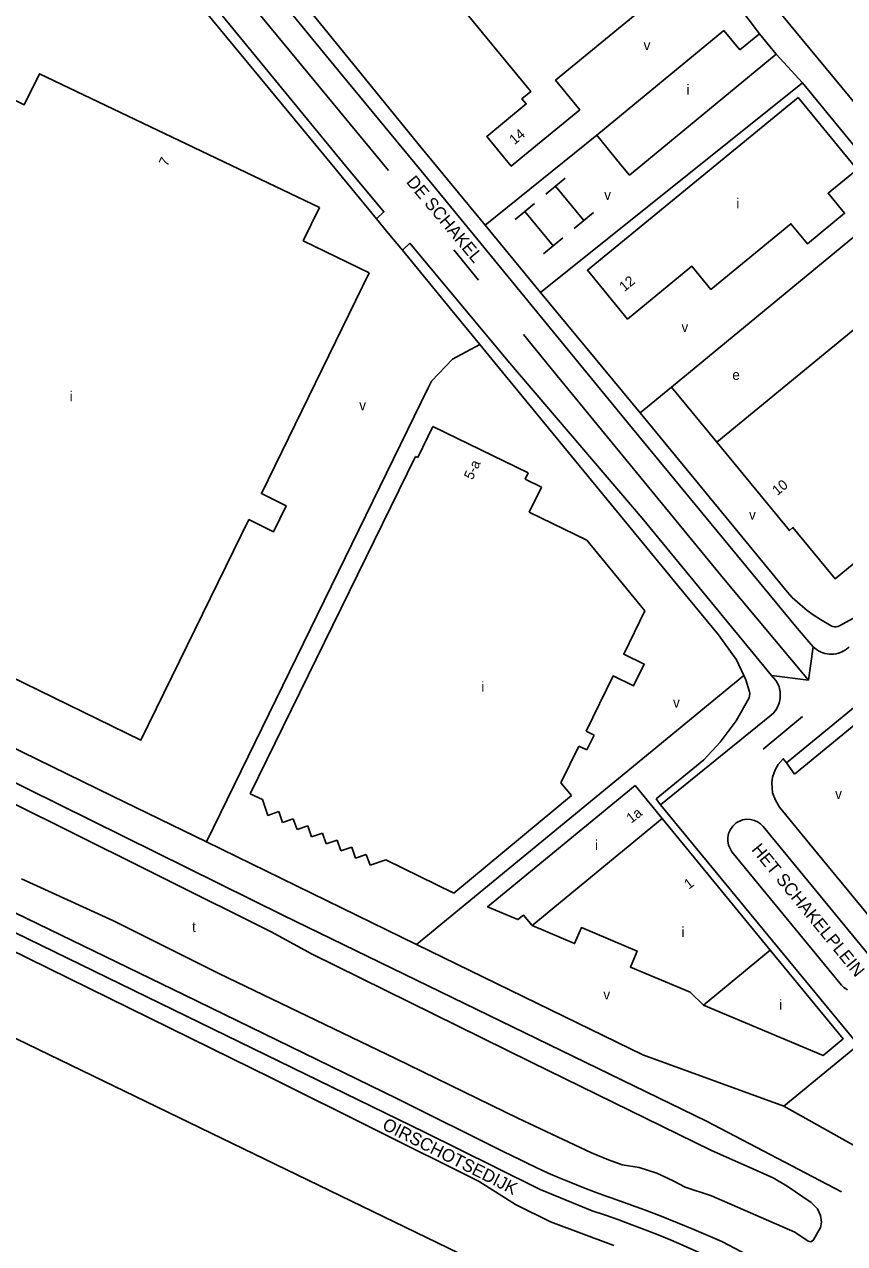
# Model space of a CAD drawing. Extents: x 156097 to 158136, y 385644 to 388348.
# Drawn here: x 156805 to 157130.5, y 386152 to 386635.8 of the extents above; entities that cross this region are included whole.
import ezdxf

# ---------------------------------------------------------------- set-up
doc = ezdxf.new("R2010")
doc.units = 0
for name, color, linetype in [('BLT_Basislijn', 7, 'Continuous'), ('BLT_Bebouwing', 7, 'Continuous'), ('BLT_Centroide', 7, 'Continuous'), ('BLT_Huisnummer', 7, 'Continuous'), ('BLT_Huisnummer_reeks', 7, 'Continuous'), ('BLT_Huisnummer_zonder_bebouwing', 7, 'Continuous'), ('BLT_Onderverdeling_panden', 7, 'Continuous'), ('BLT_Straatnaam', 7, 'Continuous'), ('BLT_Vlakafsluiter', 7, 'Continuous')]:
    doc.layers.add(name, color=color, linetype=linetype)

msp = doc.modelspace()

# ---------------------------------------------------------------- linework, layer by layer
at = {"layer": 'BLT_Basislijn'}
for p, q in [((156882.63, 386674.75), (156928.03, 386619.56)), ((157084.61, 386648.15), (157096.77, 386632.13)), ((156916.15, 386643.82), (156962.33, 386587.15)), ((157141.58, 386595.98), (157101.69, 386644.37)), ((157103.44, 386624.04), (157113.77, 386612.66)), ((156928.03, 386619.56), (156967.57, 386571.66)), ((157009.92, 386529.48), (157113.77, 386612.66)), ((157113.77, 386612.66), (157151.92, 386566.18)), ((156987.88, 386556.15), (157032.15, 386591.8)), ((156962.33, 386587.15), (156987.88, 386556.15)), ((157015.84, 386571.58), (157019.7, 386574.76)), ((156967.57, 386571.66), (157044.53, 386477.67)), ((157011.99, 386568.4), (157015.84, 386571.58)), ((157015.84, 386571.58), (157027.04, 386558)), ((157003.65, 386561.54), (157007.51, 386564.72)), ((157151.92, 386566.18), (157061.8, 386491.91)), ((157003.65, 386561.54), (156999.8, 386558.36)), ((157014.85, 386547.95), (157003.65, 386561.54)), ((157027.04, 386558), (157030.9, 386561.18)), ((156987.88, 386556.15), (157009.92, 386529.48)), ((157023.18, 386554.82), (157027.04, 386558)), ((156949.43, 386553.01), (156955.04, 386546.18)), ((157014.85, 386547.95), (157018.71, 386551.13)), ((156975.4, 386546.34), (156985.28, 386534.34)), ((157014.85, 386547.95), (157010.99, 386544.77)), ((157009.92, 386529.48), (157049.42, 386481.7)), ((157061.8, 386491.91), (157049.42, 386481.7)), ((157079.79, 386470.01), (157061.8, 386491.91)), ((157049.42, 386481.7), (157107.84, 386410.44)), ((157044.53, 386477.67), (157111.1, 386396.98)), ((157050.15, 386439.82), (157101.49, 386377.49)), ((157090.54, 386377.45), (156960.62, 386270.74)), ((157098.23, 386348.15), (157113.87, 386361.11)), ((157110.72, 386338.33), (157107.44, 386342.77)), ((157057.54, 386326.16), (157055.73, 386328.45)), ((157057.54, 386326.16), (157103.77, 386269.89)), ((156960.62, 386270.74), (156877.29, 386311.41)), ((156960.62, 386270.74), (157029.59, 386237.09)), ((157106.49, 386206.51), (157184.23, 386162.73))]:
    msp.add_line(p, q, dxfattribs=at)
for points in [[(156944.78, 386558.67), (156926.4, 386581.04), (156860.74, 386660.54), (156840.18, 386685.39), (156836.01, 386690.01), (156834.61, 386691.71), (156832.56, 386694.31), (156830.56, 386696.96), (156829.68, 386698.2)], [(156845.59, 386685.61), (156866.65, 386660.17), (156931.32, 386581.16), (156947.74, 386561.4), (156944.78, 386558.67)], [(156860.23, 386686.11), (156880.45, 386661.52), (156949.5, 386577.8)], [(156949.43, 386553.01), (156944.78, 386558.67)], [(157050.15, 386439.82), (156996.86, 386502.28), (156958.06, 386548.97), (156955.04, 386546.18)], [(156980.95, 386514.67), (156976.55, 386520.02), (156955.04, 386546.18)], [(156985.83, 386508.72), (156980.95, 386514.67)], [(157003.07, 386512.74), (157015.33, 386497.84), (157082.47, 386415.88), (157116.22, 386375.57)], [(156877.29, 386311.41), (156965.31, 386491.61), (156966.64, 386494.22), (156974.9, 386502.92), (156985.83, 386508.72)], [(157090.54, 386377.45), (157087.62, 386383.7), (157080.44, 386393.54), (157064.24, 386413.29), (156995.99, 386496.36), (156985.83, 386508.72)], [(156441.91, 386458.84), (156615.29, 386374.39), (156711.41, 386327.27), (156796.98, 386285.33), (156868.46, 386250.64), (156952.8, 386209.59), (156995.27, 386188.46)], [(156559.13, 386450.02), (156679.95, 386394.9), (156907.6, 386282.25), (157075.72, 386200.61), (157129.3, 386172.57)], [(156454.5, 386444.38), (156963.76, 386196.19), (156991.87, 386182.33)], [(156469.58, 386429.55), (156530.77, 386399.26), (156734.18, 386300.64), (156902.98, 386217.79), (156985.51, 386176.63)], [(156655.02, 386419.9), (156840.02, 386329.6)], [(157107.84, 386410.44), (157109.75, 386408.44), (157112.91, 386405.54), (157115.63, 386403.28), (157118.46, 386401.21), (157120.92, 386399.59), (157125.24, 386397.16), (157125.89, 386396.89), (157126.53, 386396.75), (157127.22, 386396.74), (157127.84, 386396.86), (157128.45, 386397.09), (157136.44, 386401.46), (157137.57, 386402.11), (157138.83, 386402.89), (157140.03, 386403.69), (157141.24, 386404.53), (157142.09, 386405.17), (157143.1, 386405.97)], [(157193.72, 386401.92), (157192.46, 386402.84), (157191.17, 386403.79), (157189.35, 386404.47), (157185.6, 386404.76), (157181.11, 386403.17), (157107.44, 386342.77)], [(156459.39, 386399.13), (157003.05, 386135.76)], [(157248.93, 386326.95), (157209.62, 386374.66), (157199.06, 386385.65), (157186.72, 386395.38), (157185.74, 386394.05), (157184.82, 386394.69), (157183.88, 386394.9), (157182.69, 386394.81), (157181.13, 386394.06), (157167.21, 386384.82), (157151.32, 386371.63), (157110.72, 386338.33)], [(157111.1, 386396.98), (157115.61, 386391.72), (157118.07, 386388.85)], [(157118.07, 386388.85), (157118.74, 386388.24), (157119.45, 386387.7), (157120.22, 386387.22), (157121.02, 386386.81), (157121.86, 386386.47), (157122.72, 386386.21), (157123.6, 386386.03), (157124.5, 386385.92), (157125.4, 386385.9), (157126.3, 386385.95), (157127.19, 386386.08), (157128.07, 386386.3), (157128.92, 386386.59), (157129.75, 386386.95), (157130.54, 386387.38), (157131.29, 386387.89), (157131.99, 386388.46), (157132.39, 386388.84)], [(157057.54, 386326.16), (157100.83, 386361.33), (157102.4, 386362.63), (157103.67, 386364.36), (157104.59, 386366.39), (157105.02, 386368.36), (157105.01, 386370.9), (157104.55, 386372.96), (157103.88, 386374.4), (157103.2, 386375.45), (157101.49, 386377.49)], [(157092.82, 386369.19), (157092.91, 386370.36), (157092.86, 386370.94), (157091.35, 386375.71), (157090.54, 386377.45)], [(157092.82, 386369.19), (157092.64, 386368.58), (157087.49, 386359.37), (157081.14, 386350.91), (157074.65, 386343.99), (157055.73, 386328.45)], [(156741.03, 386356.04), (156817.52, 386318.34), (156903.3, 386275.62), (156919.04, 386266.93), (157006.16, 386224.03), (157077.77, 386188.94), (157102.18, 386178.08), (157107.75, 386174.8), (157117.26, 386168.29), (157119.83, 386165.71), (157121.01, 386163.14), (157121.33, 386160.47), (157120.91, 386158.31), (157118.24, 386153.44), (157117.16, 386152.74), (157116.13, 386152.88), (157110.84, 386156.53), (157077.73, 386170.96), (157067.33, 386174.33), (157062.46, 386176.95), (157055.99, 386179.95), (157048.97, 386182.2), (157042.22, 386183.23), (157036.79, 386185.2), (157030.14, 386188.01), (157000.91, 386201.78), (156952.29, 386225.38), (156882.22, 386259.2), (156840.44, 386280.09), (156803.91, 386296.77)], [(157107.44, 386342.77), (157106.19, 386344.38), (157104.11, 386342.11), (157102.93, 386339.95), (157101.91, 386337.09), (157101.63, 386334.81), (157101.99, 386330.8), (157103.08, 386327.96), (157104.66, 386325.11), (157117.89, 386309.04), (157161.9, 386255.78)], [(156877.29, 386311.41), (156840.02, 386329.6)], [(157141.62, 386264.77), (157098.26, 386317.47), (157097.14, 386318.57), (157096.03, 386319.33), (157094.77, 386319.91), (157093.15, 386320.29), (157091.67, 386320.36), (157090.03, 386320.12), (157087.53, 386318.91), (157086.19, 386317.7), (157085.2, 386316.34), (157084.46, 386314.68), (157084.17, 386313.09), (157084.17, 386311.78), (157084.43, 386310.13), (157085.78, 386307.51), (157129.32, 386254.51), (157130.24, 386253.62), (157131.74, 386252.67)], [(157134.38, 386232.85), (157103.77, 386269.89)], [(157029.59, 386237.09), (157050.53, 386226.87)], [(157106.49, 386206.51), (157136.12, 386230.86), (157134.38, 386232.85)], [(157050.53, 386226.87), (157106.49, 386206.51)], [(156995.27, 386188.46), (157001.64, 386185.29)], [(156991.87, 386182.33), (157009.75, 386173.4), (157030.33, 386164.99)], [(157001.64, 386185.29), (157003.98, 386184.12), (157008.39, 386182.02), (157012.84, 386179.99), (157017.32, 386178.04), (157021.84, 386176.16), (157026.38, 386174.35), (157030.95, 386172.62), (157035.55, 386170.96), (157037.92, 386170.14), (157044.53, 386167.78), (157051.12, 386165.33), (157057.68, 386162.81), (157064.21, 386160.22), (157070.71, 386157.55), (157077.17, 386154.81), (157081.8, 386152.8), (157105, 386140.63)], [(157038.96, 386151.18), (157013.82, 386160.56), (156999.9, 386167.45), (156985.51, 386176.63)], [(157030.33, 386164.99), (157035.63, 386163.23), (157040.9, 386161.39), (157046.14, 386159.47), (157051.36, 386157.48), (157056.54, 386155.42), (157061.7, 386153.28), (157066.82, 386151.07), (157071.91, 386148.78), (157076.97, 386146.42), (157082, 386143.99), (157086.99, 386141.49), (157091.94, 386138.92), (157096.86, 386136.27), (157101.73, 386133.56), (157106.57, 386130.77), (157111.37, 386127.92), (157114.57, 386125.96)]]:
    msp.add_lwpolyline(points, dxfattribs=at)
at = {"layer": 'BLT_Bebouwing'}
for p, q in [((157032.15, 386591.8), (157082.66, 386633.45)), ((157096.77, 386632.13), (157103.44, 386624.04)), ((156922.1, 386563.13), (156915.66, 386549.94)), ((156915.66, 386549.94), (156941.81, 386537.18)), ((156967.17, 386476.28), (156961.14, 386463.97)), ((157004.95, 386457.81), (156967.17, 386476.28)), ((156960.26, 386464.36), (156894.65, 386330.53)), ((156961.14, 386463.97), (156960.26, 386464.36)), ((157003.75, 386455.35), (157004.95, 386457.81)), ((157010.2, 386452.15), (157003.75, 386455.35)), ((157005.4, 386442.29), (157010.2, 386452.15)), ((157028.24, 386431.13), (157005.4, 386442.29)), ((157051.3, 386403.13), (157028.24, 386431.13)), ((157031.12, 386353.77), (157027.94, 386355.34)), ((157028.21, 386347.87), (157031.12, 386353.77)), ((157017.94, 386334.89), (157025.05, 386349.43)), ((157025.05, 386349.43), (157028.21, 386347.87)), ((157022.13, 386329.74), (157017.94, 386334.89)), ((156894.65, 386330.53), (156899.5, 386328.16)), ((156899.5, 386328.16), (156901.65, 386321.92)), ((156975.52, 386291.04), (157022.13, 386329.74)), ((156901.65, 386321.92), (156905.96, 386323.4)), ((156905.96, 386323.4), (156907.45, 386319.08)), ((156907.45, 386319.08), (156911.75, 386320.56)), ((156911.75, 386320.56), (156913.23, 386316.27)), ((156913.23, 386316.27), (156917.53, 386317.75)), ((156917.53, 386317.75), (156919.01, 386313.43)), ((157058.14, 386320.65), (157101.06, 386268.42)), ((156919.01, 386313.43), (156923.33, 386314.91)), ((156923.33, 386314.91), (156924.81, 386310.61)), ((156924.81, 386310.61), (156929.13, 386312.09)), ((156929.13, 386312.09), (156930.62, 386307.78)), ((156930.62, 386307.78), (156934.93, 386309.25)), ((156934.93, 386309.25), (156936.41, 386304.95)), ((156936.41, 386304.95), (156940.72, 386306.43)), ((156940.72, 386306.43), (156942.2, 386302.11)), ((156942.2, 386302.11), (156948.45, 386304.26)), ((156948.45, 386304.26), (156975.52, 386291.04)), ((157074.57, 386246.6), (157069.26, 386251.77))]:
    msp.add_line(p, q, dxfattribs=at)
for points in [[(157039.69, 386679.08), (157008.89, 386653.73), (156993.01, 386673.02), (156969.52, 386653.68), (157006.07, 386609.22), (157002.5, 386606.28), (157004.19, 386604.23), (156988.5, 386591.31), (156998.23, 386579.49), (157002.08, 386582.67), (157025.46, 386601.92), (157015.82, 386613.63), (157062.16, 386651.78), (157039.69, 386679.08)], [(157082.66, 386633.45), (157089, 386625.77), (157096.77, 386632.13)], [(157103.44, 386624.04), (157045.18, 386576), (157041.78, 386580.11), (157032.15, 386591.8)], [(156712.21, 386419.62), (156702.55, 386424.34), (156752, 386525.69), (156746.37, 386528.43), (156749.68, 386535.15), (156755.29, 386532.43), (156793.03, 386609.78), (156805.01, 386603.93), (156811.03, 386616.25), (156922.1, 386563.13)], [(157135.47, 386578.26), (157123.98, 386568.81), (157130.53, 386560.85), (157115.81, 386548.73), (157109.24, 386556.7), (157077.52, 386530.62), (157069.93, 386539.82), (157044.43, 386518.9), (157028.49, 386538.25), (157112.11, 386606.77), (157135.47, 386578.26)], [(157165.83, 386540.68), (157079.79, 386470.01)], [(157079.79, 386470.01), (157108.67, 386434.94), (157110.04, 386436.12), (157126.75, 386415.79), (157181.86, 386461.2), (157183.01, 386459.8), (157212.51, 386484.05), (157165.83, 386540.68)], [(156941.81, 386537.18), (156899.1, 386449.61), (156908.92, 386444.79), (156903.9, 386434.5), (156894.07, 386439.29)], [(156894.07, 386439.29), (156851.29, 386351.74), (156799.3, 386377.13)], [(157027.94, 386355.34), (157038.65, 386377.25), (157046.72, 386373.3), (157050.96, 386381.96), (157042.88, 386385.91), (157051.3, 386403.13)], [(157006.49, 386278.21), (157003.07, 386282.38), (157000.88, 386280.58), (156988.88, 386285.67), (157047.4, 386333.71), (157058.14, 386320.65)], [(157069.26, 386251.77), (157045.53, 386261.74), (157048.17, 386268.03), (157026.09, 386277.37), (157023.4, 386271.07), (157006.49, 386278.21)], [(157101.06, 386268.42), (157129.97, 386233.24), (157121.99, 386226.68), (157074.57, 386246.6)]]:
    msp.add_lwpolyline(points, dxfattribs=at)
at = {"layer": 'BLT_Onderverdeling_panden'}
for p, q in [((157006.49, 386278.21), (157058.14, 386320.65)), ((157074.57, 386246.6), (157101.06, 386268.42))]:
    msp.add_line(p, q, dxfattribs=at)
at = {"layer": 'BLT_Vlakafsluiter'}
for p, q in [((157116.22, 386375.57), (157118.07, 386388.85)), ((157101.49, 386377.49), (157116.22, 386375.57))]:
    msp.add_line(p, q, dxfattribs=at)

# ---------------------------------------------------------------- texts
at = {"layer": 'BLT_Centroide'}
for s, p in [('v', (157050.79, 386625.59)), ('i', (157067.8, 386607.91)), ('v', (157035.16, 386566.19)), ('i', (157087.6, 386562.84)), ('v', (157065.81, 386513.77)), ('e', (157085.98, 386494.76)), ('i', (156823.04, 386486.21)), ('v', (156937.94, 386482.72)), ('v', (157092.62, 386439.27)), ('i', (156986.39, 386370.96)), ('v', (157062.46, 386364.71)), ('v', (157126.79, 386328.48)), ('i', (157031.5, 386308.16)), ('t', (156871.6, 386275.65)), ('i', (157065.8, 386273.66)), ('v', (157034.79, 386248.85)), ('i', (157104.59, 386244.75))]:
    msp.add_text(s, height=4, dxfattribs=at).set_placement(p)
at = {"layer": 'BLT_Huisnummer'}
for s, rotation, p in [('14', 39.4652, (156999.52, 386587.87)), ('7', 64.6631, (156861.78, 386579.18)), ('12', 39.469, (157043.15, 386529.54)), ('1', 37.0769, (157068.72, 386292.41))]:
    msp.add_text(s, height=4, rotation=rotation, dxfattribs=at).set_placement(p)
at = {"layer": 'BLT_Huisnummer_reeks'}
for s, rotation, p in [('5-a', 64.6631, (156982.87, 386454.8)), ('10', 39.3979, (157103.84, 386448.65))]:
    msp.add_text(s, height=4, rotation=rotation, dxfattribs=at).set_placement(p)
at = {"layer": 'BLT_Huisnummer_zonder_bebouwing'}
msp.add_text('1a', height=4, rotation=37.0769, dxfattribs=at).set_placement((157045.84, 386318.59))
at = {"layer": 'BLT_Straatnaam'}
for s, height, rotation, p in [('DE SCHAKEL', 5, 309.9798, (156956.32, 386573.18)), ('HET SCHAKELPLEIN', 5, 309.3444, (157093.35, 386308.21)), ('OIRSCHOTSEDIJK', 4.9999, 333.2009, (156946.68, 386197.64))]:
    msp.add_text(s, height=height, rotation=rotation, dxfattribs=at).set_placement(p)

doc.saveas('drawing.dxf')
